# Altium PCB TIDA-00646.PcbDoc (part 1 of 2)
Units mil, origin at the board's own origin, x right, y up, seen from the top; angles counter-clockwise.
Board outline 1574.8 x 3450 mil, 2 copper layers (Top Layer, Bottom Layer), stack 38.583 mil thick; 90 components, 120 nets, 385 pads, 272 vias.
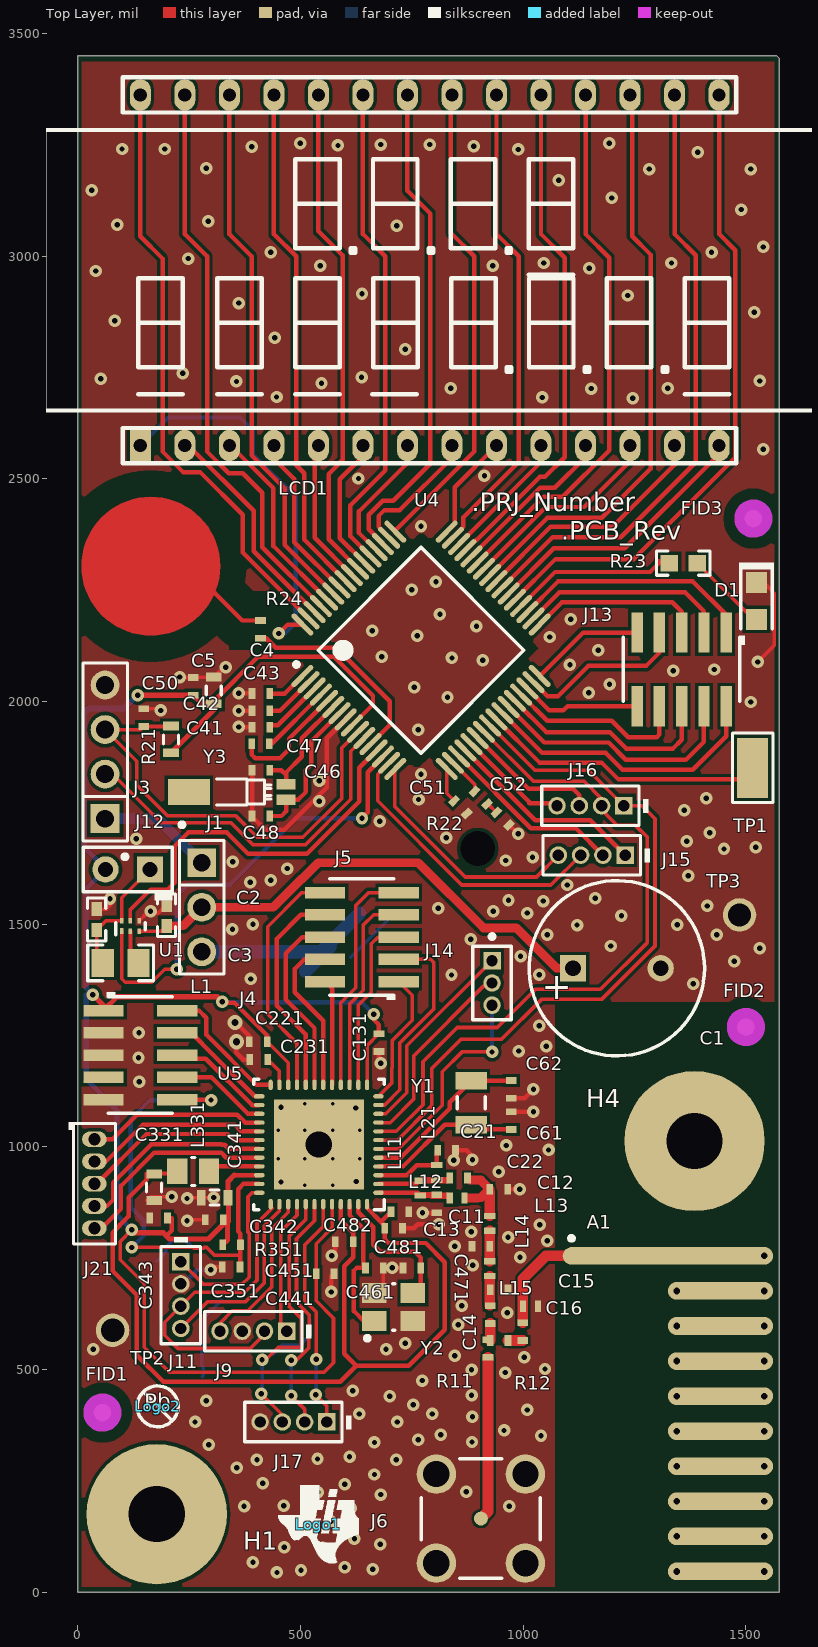
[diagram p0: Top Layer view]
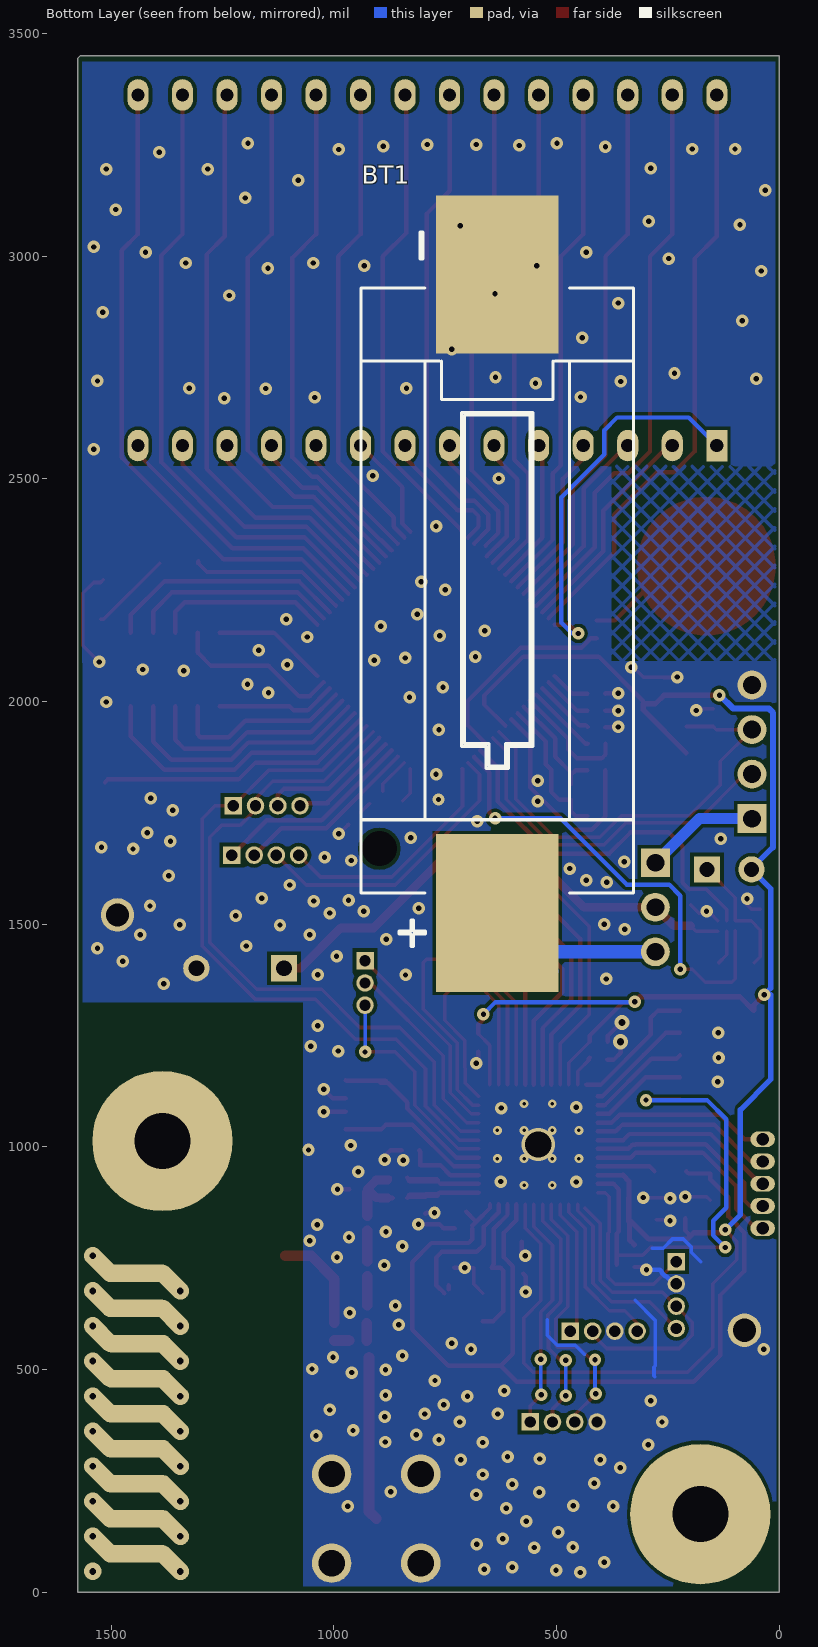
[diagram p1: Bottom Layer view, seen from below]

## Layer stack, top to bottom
Top Solder: solder mask 0.4, Solder Resist, Dk 3.5
Top Layer: signal copper 1.378
Dielectric1: core 35.8268, FR-4, Dk 4.6
Bottom Layer: signal copper 1.378
Bottom Solder: solder mask 0.4, Solder Resist, Dk 3.5

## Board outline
0,0 1574.8,0 1574.8,3445.2 1570,3450 0,3450

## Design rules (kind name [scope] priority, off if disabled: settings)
AssemblyTestPointUsage [All] p1: valid=2
Clearance Clearance_Keepouts [((IsTrack Or IsArc) And Not InPoly) And IsFree and IsKeepOut vs ((IsTrack Or IsArc) And Not InPoly) And IsFree and IsKeepOut] p1: gap=0
Clearance Clearance_BoardEdge_MountingHoles [OnCopper and InComponentClass('Mounting Holes') vs IsKeepOut] p2: gap=40
Clearance Clearance_BoardEdge_Poly [OnCopper and InPoly vs IsKeepOut] p3: gap=25
Clearance Clearance_BoardEdge [OnCopper and Not InComponentClass('Logo') and not InComponentClass('FiducialMark') and not InRegion(1000,500,4000,800) and Not IsKeepout vs IsKeepOut] p4: gap=75
Clearance Clearance_CAP [InNet('CAP_EL') vs InNet('GND')] p5: gap=59.06
Clearance Clearance_015 [InPolygon vs (InNet('NetC12_1') OR InNet('NetC13_1') OR InNet('NetC14_1') OR InNet('NetC15_2') OR InNet('NetC16_2') OR InNet('NetA1_1') OR InNet('NetJ6_1') )] p6: gap=5.91
Clearance Clearance_Poly [InPolygon] p7: gap=7.87
Clearance [All] p8: gap=7.87
ComponentClearance [All] p1: gap=10 collisioncheckmode=3 verticalgap=10 showdistances=TRUE
DiffPairsRouting [All] p1: maxlimit=100 minlimit=10 mostfreqgap=10 toplayer_minwidth=15 toplayer_maxwidth=15 toplayer_prefwidth=15 bottomlayer_minwidth=15 bottomlayer_maxwidth=15 bottomlayer_prefwidth=15 maxuncoupledlength=1000
FabricationTestPointUsage TestPointUsage [All] p1: valid=2 allowmultiple=FALSE
FabricationTestpoint Testpoint [All] p1: side=3 testpointundercomponent=TRUE minsize=40 maxsize=100 preferedsize=60 minholesize=0 maxholesize=40 preferedholesize=32 testpointgrid=1 allowsidetop=TRUE allowsidebottom=TRUE usegrid=TRUE gridtolerance=0.01
FanoutControl Fanout_LCC [IsLCC] p1: bgadir=Out bgaviamode=Centered fanoutstyle=Auto fanoutdirection=Alternating viagrid=1 // Fanout_LCC (Default Rule)
FanoutControl Fanout_BGA [IsBGA] p2: bgadir=Out bgaviamode=Centered fanoutstyle=Auto fanoutdirection=Alternating viagrid=1 // Fanout_BGA (Default Rule)
FanoutControl Fanout_Default [All] p4: bgadir=Out bgaviamode=Centered fanoutstyle=Auto fanoutdirection=Alternating viagrid=1 // Fanout_Default (Default Rule)
FanoutControl Fanout_Small [(CompPinCount < 5)] p5: bgadir=Out bgaviamode=Centered fanoutstyle=Auto fanoutdirection=OutThenIn viagrid=1 // Fanout_Small (Default Rule)
HoleSize [All] p1: absolutevalues=TRUE maxlimit=236.22 minlimit=7.87 maxpercent=80.000 minpercent=20.000
HoleSize FabricationTestpoint [All] p2 off: absolutevalues=TRUE maxlimit=100 minlimit=1 maxpercent=80.000 minpercent=20.000
HoleSize FabricationTestPointUsage [All] p3 off: absolutevalues=TRUE maxlimit=100 minlimit=1 maxpercent=80.000 minpercent=20.000
PlaneClearance [All] p1: clearance=7.87
PlaneConnect [All] p1: planeconnectstyle=Relief reliefexpansion=10 reliefentries=4 reliefconductorwidth=10 reliefairgap=10
PolygonConnect PolygonConnect_GND [HasPad('U5-49') OR HasPad('U4')] p1: connectstyle=NoConnect reliefconductorwidth=10 reliefentries=4 polygonreliefangle="90 Angle" airgapwidth=10
PolygonConnect [All] p2: connectstyle=Direct reliefconductorwidth=10 reliefentries=4 polygonreliefangle="90 Angle" airgapwidth=10
RoutingVias ThermalPadVias [IsVia and InAnyComponent] p1: holewidth=7.87 width=19.68 viastyle="Through Hole" minholewidth=7.87 minwidth=19.68 maxholewidth=15.35 maxwidth=23.62
RoutingVias [All] p2: holewidth=16 width=34 viastyle="Through Hole" minholewidth=11.81 minwidth=26 maxholewidth=40 maxwidth=65
SilkToSilkClearance [All] p1: silktosilkclearance=7.87
SilkToSolderMaskClearance [IsPad] p1: minsilkscreentomaskgap=7.87 clearancetoexposedcopper=TRUE
SolderMaskExpansion [All] p1: expansion=1.97
UnpouredPolygon [All] p1: allowunpoured=FALSE
Width [All] p1: maxlimit=100 minlimit=6 preferedwidth=10 checkconnectedcopper=TRUE
15 further rules are at their usual default settings.

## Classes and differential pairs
component class AssemblyNote: ZZ2 ZZ3 ZZ4
component class FiducialMark: FID1 FID2 FID3
component class TID_Hardware: FID1 FID2 FID3 H1 H4 Logo1 Logo2 ZZ2 ZZ3 ZZ4
component class Logo: Logo1
component class "Mounting Holes": H1 H4
component class TIDA-00646_MCU: BT1 C1 C2 C3 C4 C5 C41 C42 C43 C46 C47 C48 C50 C51 C52 D1 J1 J3 J12 J13 J14 J15 J16 L1 LCD1 R21 R22 R23 R24 TP1 TP2 TP3 U1 U4 Y3
component class TIDA-00646_RF: A1 C11 C12 C13 C14 C15 C16 C21 C22 C61 C62 C131 C221 C231 C331 C341 C342 C343 C351 C441 C451 C461 C471 C481 C482 J4 J5 J6 J9 J11 J17 J21 L11 L12 L13 L14 L15 L21 L331 R11 R12 R351 U5 Y1 Y2
component class Header: J1 J3 J4 J5 J9 J11 J12 J13 J14 J15 J16 J17 J21

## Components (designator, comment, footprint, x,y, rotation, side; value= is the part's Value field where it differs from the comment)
A1 "ANTENNA_HELICAL" ANTENNA_HELICAL 1108.46,755 r270 top locked net-tie
BT1 "1010" BAT_1010 633,2242 r90 bottom locked
C1 "EEUFM1A122" CAPPR5-10X20 1210.43,1401 r0 top locked
C2 "GRM155R60J225ME15D" 0402 199,1520 r90 top
C3 "GRM155R60J225ME15D" 0402 42,1510.38 r90 top
C4 "GRM188R61A106ME69" 0603S 305,2025 r90 top
C5 "GRM155R61E104KA87D" 0402S 259,2034 r90 top
C11 "Comment" 0402S 806,872 r90 top
C12 "GRM1555C1H2R7CA01D" 0402S 945,905 r0 top
C13 "GRM1555C1H6R2CA01D" 0402S 905,777 r180 top
C14 "GRM1555C1H3R3CA01D" 0402S 946,679 r0 top
C15 "GRM1555C1H101JA01D" 0402S 926,623 r270 top
C16 "GRM1555C1H1R0CA01D" 0402S 999,585 r270 top
C21 "GRM1555C1H101JA01D" 0402S 827.93,992.25 r180 top
C22 "GRM1555C1H3R6CA01D" 0402S 855,930 r0 top
C41 "GRM155R61E104KA87D" 0402S 411,1942 r0 top
C42 "GRM155R61E104KA87D" 0402S 411,1979 r0 top
C43 "GRM155R61E104KA87D" 0402S 411,2018 r0 top
C46 "GRM1555C1H120JA01D" 0402S 411,1846 r0 top
C47 "GRM155R61A105KE15D" 0402S 410,1905 r180 top
C48 "GRM1555C1H120JA01D" 0402S 411,1743 r0 top
C50 "GRM155R61H102KA01D" 0402S 148,1964 r90 top
C51 "GRM155R61H102KA01D" 0402S 859.14,1762.86 r135 top
C52 "GRM155R61H102KA01D" 0402S 954,1737 r135 top
C61 "Comment" 0402S 973,1059 r90 top
C62 "GRM1555C1H120JA01D" 0402S 973,1129 r270 top
C131 "GRM155R61E104KA87D" 0402S 676,1234 r270 top
C221 "GRM155R61E104KA87D" 0402S 405,1236 r180 top
C231 "Comment" 0402S 406,1196 r180 top
C331 "GRM188R60J226MEA0J" 0603S 171,909 r270 top
C341 "GRM188R60J226MEA0J" 0603S 307,886 r180 top
C342 "GRM155R61E104KA87D" 0402S 306,836 r180 top
C343 "GRM155R61E104KA87D" 0402S 181,840 r180 top
C351 "GRM155R61E104KA87D" 0402S 344,730 r180 top
C441 "GRM155R61E104KA87D" 0402S 555,715 r0 top
C451 "GRM155R61E104KA87D" 0402S 598,787 r180 top
C461 "DNM" 0402S 666,728 r0 top
C471 "DNM" 0402S 750,728 r180 top
C481 "GRM155R61E104KA87D" 0402S 709,817 r0 top
C482 "GRM155R61E104KA87D" 0402S 723,854 r0 top
D1 "LTST-C170KRKT" LED_LTST-C170 1524,2226 r90 top
FID1 "Fiducial" Fiducial10-20 55,403 r0 top
FID2 "Fiducial" Fiducial10-20 1500,1269 r0 top
FID3 "Fiducial" Fiducial10-20 1517,2411 r0 top
H1 "NY PMS 440 0025 PH" "NY PMS 440 0025 PH" 177,175 r0 top
H4 "NY PMS 440 0025 PH" "NY PMS 440 0025 PH" 1385,1013 r0 top
J1 "TSW-103-07-G-S" TSW-103-07-G-S 278,1538 r270 top
J3 "4x1 Header" TSW-104-07-G-S 61,1887 r90 top
J4 "BB02-BS101-KA8-025B00" Gradconn_BB02-BS101-xAx-025B00 140,1206 r0 top
J5 "DNP" Gradconn_BB02-BS101-xAx-025B00 637.68,1471 r180 top locked
J6 "SASF546-P26-X1" CONN_LTI_SASF546-P26-X1 905,165 r0 top locked
J9 "DNP" Preci-dip_850-xx-004-10-001101 394,586 r180 top
J11 "DNP" Preci-dip_850-xx-004-10-001101 231,667 r270 top
J12 "800-10-002-10-001000" Mill-Max_800-10-002-10-001000 112,1623 r180 top
J13 "DNP" Gradconn_BB02-BS101-xAx-025B00 1356,2072.32 r270 top
J14 "DNP" Mill-Max_850-10-003-10-001000 930,1368 r270 top
J15 "DNP" Preci-dip_850-xx-004-10-001101 1154,1655 r180 top
J16 "DNP" Preci-dip_850-xx-004-10-001101 1151,1766 r180 top
J17 "DNP" Preci-dip_850-xx-004-10-001101 484,382 r180 top
J21 "DNP" Sullins_GRPB051VWVN-RC 37,917 r270 top
L1 "LQM21PN2R2NGC" 0805_HV 96,1413 r180 top
L11 "LQW15AN18NJ00D" LQW15A_00_10 769,907 r270 top
L12 "LQW15AN7N5G00D" LQW15A_00_10 851.73,885 r0 top
L13 "LQW15AN6N8G00D" LQW15A_00_10 925,828.27 r270 top
L14 "LQW15AN6N8G00D" LQW15A_00_10 925,726.27 r270 top
L15 "LQW15AN12NJ00D" LQW15A_00_10 1016.27,642 r180 top
L21 "LQW15AN7N5G00D" LQW15A_00_10 806,942 r270 top
L331 "MLZ2012N6R8LT000" 0805_145 258.57,945 r180 top
LCD1 "DNP" LCD 140,2575 r0 top locked
Logo1 "Texas Instruments" TI_Symbol_Overlay_Small 540,152 r0 top
Logo2 "Pb-Free Symbol" Pb-Free_Overlay_Small 179,417 r0 top
R11 "CRCW04020000Z0ED" 0402S 921,547 r270 top
R12 "Comment" 0402S 946,565 r0 top
R21 "CRCW060347K0JNEA" 0603S 209,1915 r270 top
R22 "CRCW04020000Z0ED" 0402S 904.86,1784.14 r135 top
R23 "CRCW06031K20JNEA" 0603 1359.5,2311 r0 top
R24 "CRCW04020000Z0ED" 0402S 410,2162 r270 top
R351 "ERJ-2RKF1003X" 0402S 345,780 r180 top
TP1 "5015" Testpoint_Keystone_Miniature 1515,1851 r90 top
TP2 "1040" CONN_1040 78,588 r90 top
TP3 "1040" CONN_1040 1486,1521 r90 top
U1 "TPS62730DRYR" DRY0006A 118,1495.81 r90 top
U4 "DNP" PM0064A_M 770.48,2115.2 r45 top locked
U5 "CC1310F128RGZR" RGZ0048A 541.14,1005.16 r180 top locked
Y1 "FC-135 32.7680KA-A3" Epson_FC-135 883,1099 r90 top
Y2 "TSX-3225 24.0000MF20G-AC3" EPSON_TSX-3225 709,640 r90 top
Y3 "MS3V-T1R 32.768KHZ +/-20PPM 12.5PF" XTAL_MS3V-T1R 358.25,1797 r180 top
ZZ2 "These assemblies are ESD sensitive, ESD precautions shall be observed." AssemblyNote -3615,4399.11 r0 top
ZZ3 "These assemblies must be clean and free from flux and all contaminants. Use of no clean flux is not acceptable." AssemblyNote -3615,4310.56 r0 top
ZZ4 "These assemblies must comply with workmanship standards IPC-A-610 Class 2, unless otherwise specified." AssemblyNote -3615,4222 r0 top

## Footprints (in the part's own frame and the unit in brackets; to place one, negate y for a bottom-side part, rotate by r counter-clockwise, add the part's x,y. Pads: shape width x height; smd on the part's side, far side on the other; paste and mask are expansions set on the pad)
0402 [mm] "0402 from SM-752 data"
  rect 0.8x0.6 smd: 1(-0.6,0) 2(0.6,0)
  silkscreen extent -1.22,-0.52 1.22,0.52, body extent -0.55,-0.3 0.55,0.3, height 0.6
0402S [mil] "Based on C0402S footprint from PADS legacy"
  rect 15x24 smd: 1(-20,0) 2(20,0)
  body extent -22,-12 22,12, height 24
0603 [mm] "0603 from SM-752 data"
  rect 1x0.95 smd: 1(-0.8,0) 2(0.8,0)
  silkscreen extent -1.52,-0.69 1.52,0.69, body extent -0.87,-0.47 0.87,0.47, height 0.85
0603S [mil]
  rect 20x35 smd: 1(-30,0) 2(30,0)
  silkscreen extent -10,-17 10,17, body extent -34,-19 34,19, height 33
0805_145 [mm] "0805 / 1.45mm height"
  rect 1.15x1.45 smd: 1(-0.9,0) 2(0.9,0)
  silkscreen extent -0.1,-0.8 0.1,0.8, body extent -1.1,-0.72 1.1,0.72, height 1.45
0805_HV [mil] "0805 with 30mil clearance between pads"
  rect 50x63 smd: 1(-40,0) 2(40,0)
  silkscreen extent -74,-40 74,40, body extent -43,-29 43,29, height 57
ANTENNA_HELICAL [mm] "SMD, 1-Lead"
  round 1 smd paste-1 mask-1: 1(0,0)
  oval 1x12 smd paste-12 mask-12: ""(0,5.5)
  oval 1x2.414 smd far side rot 45 paste-1.5 mask-1.5: ""(0.5,10.5) ""(1.5,6.5) ""(2.5,10.5) ""(3.5,6.5) ""(4.5,10.5) ""(5.5,6.5) ""(6.5,10.5) ""(7.5,6.5) ""(8.5,10.5) ""(9.5,6.5) ""(10.5,10.5) ""(11.5,6.5) ""(12.5,10.5) ""(13.5,6.5) ""(14.5,10.5) ""(15.5,6.5) ""(16.5,10.5) ""(17.5,6.5)
  oval 1x4 smd far side paste-4 mask-4: ""(1,8.5) ""(3,8.5) ""(5,8.5) ""(7,8.5) ""(9,8.5) ""(11,8.5) ""(13,8.5) ""(15,8.5) ""(17,8.5)
  oval 1x6 smd paste-6 mask-6: ""(2,8.5) ""(4,8.5) ""(6,8.5) ""(8,8.5) ""(10,8.5) ""(12,8.5) ""(14,8.5) ""(16,8.5) ""(18,8.5)
  silkscreen extent -1.12,-0.12 -0.88,0.13
AssemblyNote [mil] "Assembly Note"
BAT_1010 [mm] "Keystone"
  round 0.94 hole 1.994 unplated: 0(-14.54,6.73)
  rect 9x7 smd: 1(-18.21,0) 2(18.21,0)
  silkscreen extent -20.12,-7.77 20.64,7.77, body extent -21.7,-7.77 22.07,7.77, height 15.06
CAPPR5-10X20 [mm] "Capacitor, Electrolytic, Radial; Body 10 x 20 mm (Dia.xH typ); Pin Spacing 5 mm (typ)"
  rect 1.5x1.5 hole 0.9: 1(-2.5,0)
  round 1.5 hole 0.9: 2(2.5,0)
  silkscreen extent -5,-5 5,5, body extent -5.01,-5.01 5.01,5.01, height 22
CONN_1040 [mil] "Test Point, PC  test point Terminal"
  round 75 hole 52: 1(0,0)
  body extent -55,-12 55,13, height 276
CONN_LTI_SASF546-P26-X1 [mm]
  round 0.8 smd: 1(0,0)
  round 2.25 hole 1.5 mask+0.051: 2(-2.54,2.54) 3(-2.54,-2.54) 4(2.54,-2.54) 5(2.54,2.54)
  silkscreen extent -3.4,-3.4 3.4,3.4, body extent -3.17,-3.17 3.17,3.17, height 12.53
DRY0006A [mm] "PSON, 6-Leads, Body 1x1.45mm, Pitch 0.5mm, TI Recommended"
  rect 0.35x0.2 smd: 1(-0.275,0.5)
  rect 0.3x0.2 smd: 2(-0.3,0) 3(-0.3,-0.5) 4(0.3,-0.5) 5(0.3,0) 6(0.3,0.5)
  silkscreen extent -0.5,-0.85 0.2,0.85, body extent -0.53,-0.75 0.53,0.75, height 0.61
Epson_FC-135 [mm] "SMD, 2-Leads, Body 3.2x1.5mm"
  rect 1x1.8 smd: 1(-1.25,0) 2(1.25,0)
  silkscreen extent -0.35,-0.8 0.35,0.8, body extent -1.65,-0.8 1.65,0.8, height 0.9
EPSON_TSX-3225 [mm] "SMD, 4-Leads, Body 2.65x3.35mm, Height 0.6mm"
  rect 1.15x1.4 smd: 1(-0.8,1.1) 2(-0.8,-1.1) 3(0.8,-1.1) 4(0.8,1.1)
  silkscreen extent -1.9,-0.05 1.33,1.62, body extent -1.33,-1.68 1.33,1.68, height 0.61
Fiducial10-20 [mm]
  round 1 smd mask+0.5: 1(0,0)
  Top Layer keep-out circle w1.178: c0,0 r0.5
Gradconn_BB02-BS101-xAx-025B00 [mm] "Header, 1.27mm, 5x2, SMT"
  rect 2.3x0.65 smd: 1(-2.1,2.54) 2(2.1,2.54) 3(-2.1,1.27) 4(2.1,1.27) 5(-2.1,0) 6(2.1,0) 7(-2.1,-1.27) 8(2.1,-1.27) 9(-2.1,-2.54) 10(2.1,-2.54)
  silkscreen extent -1.92,-3.32 1.83,3.6, body extent -2.75,-3.32 2.75,3.32, height 4.25
LCD [mm]
  rect 1.2x1.8 hole 0.75: 1(0,0)
  oval 1.2x1.8 hole 0.75: 2(2.54,0) 3(5.08,0) 4(7.62,0) 5(10.16,0) 6(12.7,0) 7(15.24,0) 8(17.78,0) 9(20.32,0) 10(22.86,0) 11(25.4,0) 12(27.94,0) 13(30.48,0) 14(33.02,0) 15(33.02,20) 16(30.48,20) 17(27.94,20) 18(25.4,20) 19(22.86,20) 20(20.32,20) 21(17.78,20) 22(15.24,20) 23(12.7,20) 24(10.16,20) 25(7.62,20) 26(5.08,20) 27(2.54,20) 28(0,20)
  silkscreen extent -5.5,-1 38.5,21
LED_LTST-C170 [mm] "LITE-ON"
  rect 1.2x1.2 smd: 1(-1.05,0) 2(1.05,0)
  silkscreen extent -1.6,-1 2.2,1, body extent -1.05,-0.67 1.05,0.67, height 1.1
LQW15A_00_10 [mm] "Murata"
  rect 0.35x0.65 smd: 1(-0.425,0) 2(0.425,0)
  body extent -0.55,-0.35 0.55,0.35, height 0.6
Mill-Max_800-10-002-10-001000 [mm] "Mill-Max"
  rect 1.5x1.5 hole 0.85: 1(-1.27,0)
  round 1.5 hole 0.85: 2(1.27,0)
  silkscreen extent -2.54,-1.27 2.54,1.78, body extent -2.54,-1.27 2.54,1.27, height 8.13
Mill-Max_850-10-003-10-001000 [mm] "Header, 1.27 mm, 3x1, Gold, Straight, TH"
  rect 1x1 hole 0.65: 1(-1.27,0)
  round 1 hole 0.65: 2(0,0) 3(1.27,0)
  silkscreen extent -2.77,-1.1 2.09,1.1, body extent -2.1,-1.1 2.1,1.1, height 5.21
"NY PMS 440 0025 PH" [mm] "4-40 nylon screw and mounting hole"
  round 8 hole 3.2: 1(0,0)
  body extent -3.3,-3.3 3.3,3.3, height 2.69
Pb-Free_Overlay_Small [mil]
  silkscreen extent -46,-46 46,46
PM0064A_M [mm] "Thin QFP, 64-Leads, Body 10x10mm, Pitch 0.5mm, IPC Low Density"
  oval 1.65x0.3 smd: 1(-5.825,3.75) 2(-5.825,3.25) 3(-5.825,2.75) 4(-5.825,2.25) 5(-5.825,1.75) 6(-5.825,1.25) 7(-5.825,0.75) 8(-5.825,0.25) 9(-5.825,-0.25) 10(-5.825,-0.75) 11(-5.825,-1.25) 12(-5.825,-1.75) 13(-5.825,-2.25) 14(-5.825,-2.75) 15(-5.825,-3.25) 16(-5.825,-3.75) 33(5.825,-3.75) 34(5.825,-3.25) 35(5.825,-2.75) 36(5.825,-2.25) 37(5.825,-1.75) 38(5.825,-1.25) 39(5.825,-0.75) 40(5.825,-0.25) 41(5.825,0.25) 42(5.825,0.75) 43(5.825,1.25) 44(5.825,1.75) 45(5.825,2.25) 46(5.825,2.75) 47(5.825,3.25) 48(5.825,3.75)
  oval 0.3x1.65 smd: 17(-3.75,-5.825) 18(-3.25,-5.825) 19(-2.75,-5.825) 20(-2.25,-5.825) 21(-1.75,-5.825) 22(-1.25,-5.825) 23(-0.75,-5.825) 24(-0.25,-5.825) 25(0.25,-5.825) 26(0.75,-5.825) 27(1.25,-5.825) 28(1.75,-5.825) 29(2.25,-5.825) 30(2.75,-5.825) 31(3.25,-5.825) 32(3.75,-5.825) 49(3.75,5.825) 50(3.25,5.825) 51(2.75,5.825) 52(2.25,5.825) 53(1.75,5.825) 54(1.25,5.825) 55(0.75,5.825) 56(0.25,5.825) 57(-0.25,5.825) 58(-0.75,5.825) 59(-1.25,5.825) 60(-1.75,5.825) 61(-2.25,5.825) 62(-2.75,5.825) 63(-3.25,5.825) 64(-3.75,5.825)
  silkscreen extent -5.72,-4.15 4.15,4.57, body extent -6,-6 6,6, height 1.49
Preci-dip_850-xx-004-10-001101 [mm] "Preci-dip"
  rect 1x1 hole 0.65: 1(-1.905,0)
  round 1 hole 0.65: 2(-0.635,0) 3(0.635,0) 4(1.905,0)
  silkscreen extent -3.33,-1.12 2.78,1.12, body extent -2.74,-1.1 2.74,1.1, height 5.2
RGZ0048A [mm] "QFN, 48-Leads, Body 7x7mm, Pitch 0.5mm, Thermal Pad 5.15X5.15mm, TI recommended"
  oval 0.6x0.24 smd: 1(-3.4,2.75) 2(-3.4,2.25) 3(-3.4,1.75) 4(-3.4,1.25) 5(-3.4,0.75) 6(-3.4,0.25) 7(-3.4,-0.25) 8(-3.4,-0.75) 9(-3.4,-1.25) 10(-3.4,-1.75) 11(-3.4,-2.25) 12(-3.4,-2.75) 25(3.4,-2.75) 26(3.4,-2.25) 27(3.4,-1.75) 28(3.4,-1.25) 29(3.4,-0.75) 30(3.4,-0.25) 31(3.4,0.25) 32(3.4,0.75) 33(3.4,1.25) 34(3.4,1.75) 35(3.4,2.25) 36(3.4,2.75)
  oval 0.24x0.6 smd: 13(-2.75,-3.4) 14(-2.25,-3.4) 15(-1.75,-3.4) 16(-1.25,-3.4) 17(-0.75,-3.4) 18(-0.25,-3.4) 19(0.25,-3.4) 20(0.75,-3.4) 21(1.25,-3.4) 22(1.75,-3.4) 23(2.25,-3.4) 24(2.75,-3.4) 37(2.75,3.4) 38(2.25,3.4) 39(1.75,3.4) 40(1.25,3.4) 41(0.75,3.4) 42(0.25,3.4) 43(-0.25,3.4) 44(-0.75,3.4) 45(-1.25,3.4) 46(-1.75,3.4) 47(-2.25,3.4) 48(-2.75,3.4)
  rect 5.15x5.15 smd paste-2.6: 49(0,0)
  silkscreen extent -3.73,-3.72 3.73,3.72, body extent -3.58,-3.57 3.57,3.58, height 1.01
Sullins_GRPB051VWVN-RC [mm] "SULLINS"
  oval 0.9x1.4 hole 0.7: 1(-2.54,0) 2(-1.27,0) 3(0,0) 4(1.27,0) 5(2.54,0)
  silkscreen extent -3.53,-1.48 3.45,1.2, body extent -3.42,-1.17 3.42,1.17, height 4.2
Testpoint_Keystone_Miniature [mil] "Miniature SMT test point"
  rect 135x70 smd: 1(0,0)
  silkscreen extent -78,-46 78,45, body extent -52,-20 52,20, height 61
TI_Symbol_Overlay_Small [mil]
  silkscreen extent -90,-88 91,88
TSW-103-07-G-S [mm]
  rect 1.65x1.65 hole 1.016 mask+0: 1(-2.54,0)
  round 1.65 hole 1.016 mask+0: 2(0,0) 3(2.54,0)
  silkscreen extent -4.83,-1.27 3.81,1.27, body extent -3.81,-1.27 3.81,1.27, height 8.38
TSW-104-07-G-S [mm]
  rect 1.65x1.65 hole 1.016 mask+0: 1(-3.81,0)
  round 1.65 hole 1.016 mask+0: 2(-1.27,0) 3(1.27,0) 4(3.81,0)
  silkscreen extent -6.1,-1.27 5.08,1.27, body extent -5.08,-1.27 5.08,1.27, height 8.38
XTAL_MS3V-T1R [mm] "Micro Crystal Switzerland recommended land pattern"
  rect 1.1x0.6 smd: 1(-2.775,0.45) 2(-2.775,-0.45)
  rect 2.4x1.5 smd: 3(2.775,0)
  silkscreen extent -1.9,-0.74 1.2,0.74, body extent -3.05,-0.74 3.65,0.74, height 1.42

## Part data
A1: "PCB Antenna. There is nothing to buy or mount."
BT1: "Battery Holder, Nylon, CR2, SMT"
C1: "CAP, AL, 1200 µF, 10 V, +/- 20%, TH"
C2 C3: "CAP, CERM, 2.2 µF, 6.3 V, +/- 20%, X5R, 0402"
C4: "CAP, CERM, 10 µF, 10 V, +/- 20%, X5R, 0603"
C5 C41 C42 C43 C131 C221 C342 C343 C351 C441 C451 C481 C482: "CAP, CERM, 0.1 µF, 25 V, +/- 10%, X5R, 0402"
C11: library part GRM1555C1H3R6CA01D, "CAP, CERM, 3.6 pF, 50 V, +/- 5%, C0G/NP0, 0402"
C12: "CAP, CERM, 2.7 pF, 50 V, +/- 5%, C0G/NP0, 0402"
C13: "CAP, CERM, 6.2 pF, 50 V, +/- 5%, C0G/NP0, 0402"
C14: "CAP, CERM, 3.3 pF, 50 V, +/- 5%, C0G/NP0, 0402"
C15 C21: "CAP, CERM, 100 pF, 50 V, +/- 5%, C0G/NP0, 0402"
C16: "CAP, CERM, 1 pF, 50 V, +/- 5%, C0G/NP0, 0402"
C22: "CAP, CERM, 3.6 pF, 50 V, +/- 5%, C0G/NP0, 0402"
C46 C48 C62: "CAP, CERM, 12 pF, 50 V, +/- 5%, C0G/NP0, 0402"
C47: "CAP, CERM, 1 µF, 10 V, +/- 10%, X5R, 0402"
C50 C51 C52: "CAP, CERM, 1000 pF, 50 V, +/- 10%, X5R, 0402"
C61 C461 C471: library part GRM1555C1H120JA01D, "CAP, CERM, 12 pF, 50 V, +/- 5%, C0G/NP0, 0402"
C231: library part GRM155R61A105KE15D, "CAP, CERM, 1 µF, 10 V, +/- 10%, X5R, 0402"
C331 C341: "CAP, CERM, 22 µF, 6.3 V, +/- 20%, X5R, 0603"
D1: "LED, Green, SMD"
FID1 FID2 FID3: "Fiducial mark.  There is nothing to buy or mount."
H1 H4: "Machine Screw, Round, #4-40 x 1/4, Nylon, Philips panhead"
J1: "Header, TH, 100mil, 3x1, Gold plated, 230 mil above insulator"
J3: library part TSW-104-07-G-S, "Header, TH, 100mil, 4x1, Gold plated, 230 mil above insulator"
J4: "Header, 1.27mm, 5x2, SMT"
J5 J13: library part BB02-BS101-KA8-025B00, "Header, 1.27mm, 5x2, SMT"
J6: "Connector, SMA,Vertical, Thru hole w/SMT center pin"
J9 J11 J15 J16 J17: library part 850-10-004-10-001101, "Header, 50mil, 4x1, Gold, TH"
J12: "Header, 100mil, 2x1, TH"
J14: library part 850-10-003-10-001000, "Header, 50mil, 3x1, Gold, TH"
J21: library part GRPB051VWVN-RC, "Header, 50mil, 5x1, Gold, TH"
L1: "Inductor, Shielded, Ferrite, 2.2 µH, 0.8 A, 0.23 ohm, SMD"
L11: "Inductor, Wirewound, 18 nH, 0.37 A, 0.27 ohm, SMD"
L12 L21: "Inductor, Wirewound, 7.5 nH, 0.57 A, 0.13 ohm, SMD"
L13 L14: "Inductor, Wirewound, 6.8 nH, 0.7 A, 0.09 ohm, SMD"
L15: "Inductor, Wirewound, 12 nH, 0.5 A, 0.14 ohm, SMD"
L331: "Inductor, Multilayer, Ferrite, 6.8 µH, 0.11 A, 0.25 ohm, SMD"
LCD1: library part LCD_4MUX, "BTL002 4COM LCD"
Logo1: library part TI_Logo, "Texas Instrument Corporate Signature"
Logo2: library part Pb-Free
R11 R22 R24: "RES, 0, 5%, 0.063 W, 0402"
R12: library part CRCW04020000Z0ED, "RES, 0, 5%, 0.063 W, 0402"
R21: "RES, 47 k, 5%, 0.1 W, 0603"
R23: "RES, 1.2 k, 5%, 0.1 W, 0603"
R351: "RES, 100 k, 1%, 0.1 W, 0402"
TP1: "Test Point, Miniature, SMT"
TP2 TP3: "TEST POINT SLOTTED .118\", TH"
U1: "Buck Step Down Regulator with 1.9 to 3.9 V Input and 2.1 V Output, -40 to 85 degC, 6-Pin SON (DRY), Green (RoHS & no Sb/Br)"
U4: library part MSP430G60x1, "16-bit Ultra-Low-Power MCU"
U5: "Sub-1 GHz and 2.4 GHz Multi-standard RF IC Family, RGZ0048A"
Y1: "Crystal, 32.768 KHz, 12.5 pF, SMD"
Y2: "Crystal, 24 MHz, 9 pF, SMD"
Y3: "Crystal, 32.768kHz, 12.5pF, SMD"
ZZ2 ZZ3 ZZ4: library part AssemblyNote

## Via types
v1: diameter 28, hole 12, Top Layer to Bottom Layer, 238 vias
v2: diameter 39.37, hole 14.96, Top Layer to Bottom Layer, 19 vias
v3: diameter 19.68, hole 7.87, Top Layer to Bottom Layer, 12 vias
v4: diameter 34, hole 16, Top Layer to Bottom Layer, 2 vias
v5: diameter 74.8, hole 59.06, Top Layer to Bottom Layer, 1 vias

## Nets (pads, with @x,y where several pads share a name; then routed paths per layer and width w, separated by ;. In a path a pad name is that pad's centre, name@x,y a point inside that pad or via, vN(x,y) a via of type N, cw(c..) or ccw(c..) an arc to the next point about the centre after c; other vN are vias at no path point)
ACLK: J15.3 U4.15 | length 658.3
  Top Layer w8: U4.15@698.79,1862.56 673,1836.77 673,1777 862,1588 1062,1588 J15.3@1129,1655
BAT_IN: BT1.1 J1.3 | length 609.6
  Bottom Layer w8: BT1.1@613,1426 BT1.1@713,1526
  Bottom Layer w30: J1.3@278,1438 545.93,1438 BT1.1@633,1525.07 ; BT1.1@511,1394 BT1.1@565.5,1448.5
BYP_TPS: U1.5 U4.13 | length 858.6
  Top Layer w7.87: U1.5@118,1507.62 118,1533 163,1578 202,1578
  Top Layer w10: 202,1578 217,1593 217,1675 248,1706 334,1706 382,1658 514.31,1658 632,1775.69 632,1851.45 U4.13@670.95,1890.4
CAP_EL: R24.1 | length 127.3
  Top Layer w10: 308,2243 369,2182 R24.1@410,2182
CAPT: R24.2 U4.12 | length 462.9
  Top Layer w10: R24.2@410,2142 423,2142 444,2121 580,2121 700,2001 700,1947.29 U4.12@657.03,1904.32
CAPT1: R22.2 U4.18 | length 84.4
  Top Layer w8: U4.18@842.16,1862.56 890.72,1814.01 R22.2@890.72,1798.28
CAPT2: C51.2 U4.17 | length 78.6
  Top Layer w8: U4.17@828.24,1848.64 828.24,1793.76 C51.2@845,1777
DCDC_SW: L331.1 U5.33 | length 132
  Top Layer w10: L331.1@279.87,945 290.81,955.94 U5.33@407.28,955.94
"DIO16 / JTAG TDO": J4.6 U5.26 | length 231.1
  Top Layer w10: J4.6@222.68,1206 230.68,1198 287,1198 391.26,1093.74 U5.26@407.28,1093.74
"DIO17 / JTAG TDI": J4.8 U5.27 | length 218.5
  Top Layer w10: J4.8@222.68,1156 299.83,1156 381.78,1074.05 U5.27@407.28,1074.05
DIO_1: J14.3 U5.6 | length 494.5
  Top Layer w8: U5.6@675,995.31 720.45,995.31 818.13,1092.99 818.13,1168.68 862.44,1213 v1(930,1213)
  Bottom Layer w8: v1(930,1213) J14.3@930,1318
DIO_4: J14.2 U5.9 | length 441.7
  Top Layer w8: U5.9@675,1054.37 701.37,1054.37 754.62,1107.62 754.62,1204.62 911,1361 923,1361 J14.2@930,1368
DIO_5: J14.1 U5.10 | length 459.3
  Top Layer w8: U5.10@675,1074.05 691.6,1074.05 738.75,1121.2 738.75,1226.75 J14.1@930,1418
DIO_6: J5.3 U5.11 | length 461.3
  Top Layer w8: U5.11@675,1093.74 688.85,1093.74 722.88,1127.77 722.88,1233.32 799,1309.44 799,1414 792,1421 J5.3@720.35,1421
DIO_7: J5.1 U5.12 | length 301.8
  Top Layer w8: U5.12@675,1113.42 675.07,1113.42 705,1143.36 705,1176.41 705.87,1177.28 705.87,1238.76 751,1283.89 751,1340.35 J5.1@720.35,1371
DIO_8: J5.5 U5.14 | length 396.7
  Top Layer w8: U5.14@629.72,1139.01 629.72,1317.72 659,1347 659,1456 674,1471 J5.5@720.35,1471
DIO_9: J5.7 U5.15 | length 460.7
  Top Layer w8: U5.15@610.04,1139.01 610.04,1320.48 641.13,1351.57 641.13,1498.13 664,1521 J5.7@720.35,1521
DIO_10: J5.9 U5.16 | length 525.3
  Top Layer w8: U5.16@590.35,1139.01 590.35,1323.24 624.03,1356.92 624.03,1542.03 653,1571 J5.9@720.35,1571
DIO_11: J5.2 U5.17 | length 238.5
  Top Layer w10: J5.2@555,1371 570.67,1355.33 U5.17@570.67,1139.01
DIO_12: J5.4 U5.18 | length 363.6
  Top Layer w10: U5.18@550.98,1139.01 550.98,1283.02 487.2,1346.8 487.2,1399.54 508.66,1421 J5.4@555,1421
DIO_13: J5.6 U5.19 | length 424.9
  Top Layer w10: U5.19@531.3,1139.01 531.3,1266.7 467,1331 467,1434 504,1471 J5.6@555,1471
DIO_14: J5.8 U5.20 | length 485.4
  Top Layer w10: U5.20@511.61,1139.01 511.61,1252.39 447,1317 447,1467.44 500.56,1521 J5.8@555,1521
DIO_15: J5.10 U5.21 | length 543.2
  Top Layer w8: U5.21@491.93,1139.01 491.93,1232.07 426,1298 426,1494 503,1571 J5.10@555,1571
DIO_18: J21.1 U5.28 | length 400.4
  Top Layer w10: J21.1@37,1017 77.68,1017 132.68,1072 358,1072 375.63,1054.37 U5.28@407.28,1054.37
DIO_19: J21.2 U5.29 | length 411
  Top Layer w10: J21.2@37,967 63,967 146,1050 351.68,1050 367,1034.68 U5.29@407.28,1034.68
DIO_20: J21.3 U5.30 | length 422.3
  Top Layer w10: J21.3@37,917 42.22,917 154,1028.78 336.76,1028.78 350.54,1015 U5.30@407.28,1015
DIO_21: J21.4 U5.31 | length 455.2
  Top Layer w10: J21.4@37,867 65.18,867 78.76,880.57 78.76,919.45 165,1005.7 165,1006 322,1006 323.13,1004.87 329.4,1004.87 338.96,995.31 U5.31@407.28,995.31
DIO_22: J21.5 U5.32 | length 475.5
  Top Layer w10: J21.5@37,817 53,817 96.63,860.63 96.63,912.05 171.58,987 322,987 333.37,975.63 U5.32@407.28,975.63
DIO_28: J17.3 U5.41 | length 605.4
  Top Layer w8: v1(412,445) 459,398 J17.3@459,382 ; v1(413.54,521.87) 421.87,521.87 449.87,549.87 497.87,549.87 502.04,554.04 502.04,613.96 475,641 475,800.13 511.61,836.74 U5.41@511.61,871.3
  Bottom Layer w8: v1(412,445) 412,454 413.54,455.54 v1(413.54,521.87)
DIO_29: J17.2 U5.42 | length 554.2
  Top Layer w8: v1(479,441) 509,411 J17.2@509,382 ; v1(479,521) 491.44,521 517.91,547.46 517.91,585.35 519.28,586.72 519.28,622.28 493.13,648.43 493.13,649.87 490.87,652.13 490.87,793.55 531.3,833.98 U5.42@531.3,871.3
  Bottom Layer w8: v1(479,441) v1(479,521)
DIO_30: J17.1 U5.43 | length 530.4
  Top Layer w8: v1(534,443) 559,418 J17.1@559,382 ; v1(535,523) 535.15,523.15 535.15,628.85 509,655 509,779 550.98,820.98 U5.43@550.98,871.3
  Bottom Layer w8: v1(534,443) 535,442 v1(535,523)
GND: BT1.2 C1.2 C2.2 C3.2 C4.2 C5.2 C11.1 C12.2 C13.2 C14.2 C21.1 C41.1 C42.1 C43.1 C46.1 C48.1 C50.2 C51.1 C52.1 C61.2 C62.2 C131.2 C221.2 C231.2 C331.2 C341.2 C342.2 C343.2 C351.2 C441.2 C451.2 C461.2 C471.2 C481.2 C482.2 D1.2 J3.4 J4.3 J4.5 J4.9 J6.2 J6.3 J6.4 J6.5 J9.3 J11.2 J17.4 L15.1 TP2.1 TP3.1 U1.4 U4.8 U5.49 Y2.2 Y2.4 | length 2477.5
  Top Layer w7.87: C3.2@42,1534 63,1534 v1@73,1544 ; U1.4@137.69,1507.62 155.06,1525 180.38,1525 C2.2@199,1543.62 ; Y2.4@665.69,671.5 686,691.8 C461.2@686,728 v1(706,728)
  Top Layer w8: C50.2@148,1984 182,1984 v1(186,1980) ; C331.2@155,880 163,888 v1(211,888) ; v1(229,2055) 230,2054 C5.2@259,2054 260,2055 C4.2@305,2055 327,2077 v1(332,2077) ; v1(245,834) 247,836 276,836 ; v1(245,884) 247,886 C341.2@277,886 v1(305,886) v1@307,886 ; D1.2@1518,2273.34 D1.2@1524,2267.34 1539.66,2267.34 1564,2243 1564,2126 v1(1527,2089)
  Top Layer w10: v1@296,722 v1(298,724) 304,730 C351.2@324,730 ; v4(353,1279) 354,1280 385,1249 C221.2@385,1236 ; v4(356,1236) 356,1211 371,1196 C231.2@386,1196 ; v1@360,1979 v1(361.13,1979) C42.1@391,1979 ; v1(361,1943) 362,1942 C41.1@391,1942 ; v1(361.13,2019) 390,2019 C43.1@391,2018 ; C46.1@391,1846 C48.1@391,1743 391,1741.86 420.99,1711.87 463.87,1711.87 559,1807 559,1917.64 U4.8@601.36,1960 ; v1(569,674) 569,709 C441.2@575,715 ; v1(570,755) 578,763 C451.2@578,787 ; C131.2@676,1214 676,1193 681,1188 v1(680,1188) ; v1(706,728) C471.2@730,728 ; C481.2@729,817 754,817 763,826 v1(810,826) ; v1(774,852) 793,852 C11.1@795,850 ; C21.1@847.93,992.25 872.75,992.25 886,979 v1(886,971) ; C12.2@965,905 v1(992,905) ; C52.1@968.14,1722.86 988,1703 v1(989,1703) ; C61.2@973,1079 v1(1023,1079) ; C62.2@973,1109 1003,1109 v1(1023,1129)
  Bottom Layer w8: 176,742 197,763 197,775 215,793 239.41,793 260.28,772.13 284.87,772.13 ; 279,484 281,486 281,505 278,508 278,610 323,655 ; 438,534 458,554 498.11,554 521,576.89 521,611
  Bottom Layer w10: J11.2@231,692 236,692 253.44,709.44 256.02,709.44 263.56,716.98 263.56,719.56 268,724 v1(298,724) v1@297,723
  other v1: 447,44 501,49 662,51 599,56 393,67 550,100 463,101 679,107 621,120 496,134 568,159 613,188 373,193 969,193 462,194 680,219 539,224 872,225 599,242 415,244 666,264 357,279 402,297 715,297 538,299 610,304 294,331 666,336 885,337 764,342 1040,351 815,353 957,363 263,382 717,382 886,394 632,400 796,400 1009,409 753,421 288,430 700,440 884,442 617,452 773,475 960,493 884,499 1049,501 1002,527 846,531 34.5,545 692,545 735,559 854,600 964,627 861.76,643.23 887,734 993,752 846,777 1054,789 966,797 883,809 1037,825 456,921 625,922 945,944 844,970 1057,993 962,1003 624,1087 456,1089 138,1146 136,1200 990,1215 1052,1226 137,1256 1036,1272 1382,1366 388,1377 839,1386 1036.09,1386.1 1474,1417 994,1428 1531,1446 1197,1451 882,1466 1054,1476 1435,1476 347,1489 1121,1498 1346,1499 393,1500 1220.69,1518.77 1009,1525 163,1529 933,1529 809,1536 1413,1541 1045,1552 967,1554 72,1557 1162,1558 1099,1588 387,1594 433,1599 1371,1609 470,1625 348,1640 961,1643 1021,1650 1451,1669 1522,1673 1367,1686 131,1692 827,1694 1419,1705 678,1731 1362,1756 542,1776 765,1780 1411,1783 542,1822 770.48,1836.81 764,1937 1511,1999 830,2010 1147,2020 755,2032 1194,2039 1337,2069 1429,2072 1105,2083 909,2093 840,2098 682,2101 1168.57,2115.2 1060,2145 762,2148 661,2159 895,2169 1107,2185 813,2196 750,2251 804,2269 770.48,2393.59 630,2501 913,2507 1539,2567 1246,2681 1043,2683 446,2684 1153,2703 837,2704 1325,2704 547,2715 356,2719 1531,2720 51,2725 637,2728 235,2737 735,2791 442,2817 83,2855 1519,2874 361,2895 1235,2912 638,2916 40,2967 1148,2973 544,2979 932,2979 1046,2985 1333,2985 248,2995 433,3009 1423,3009 1539,3021 716,3069 88,3071 293,3079 1490,3105 1199,3131 31,3148 1080,3171 1283,3196 1511,3196 288,3198 1392,3234 989,3240 99,3241 195,3241 390,3246 889,3247 584,3249 680,3251 790,3251 499,3254 1193,3254
  other v3: 509.51,913.62 572.78,913.62 449.61,973.52 509.51,973.52 572.78,973.52 632.68,973.52 449.61,1036.79 509.51,1036.79 572.78,1036.79 632.68,1036.79 509.51,1096.69 572.78,1096.69
  other v5: 541.14,1005.16
JTAG_TCK: J4.4 U5.25 | length 243.7
  Top Layer w10: J4.4@222.68,1256 254.27,1256 304,1206.28 396.85,1113.42 U5.25@407.28,1113.42
JTAG_TMS: J4.2 U5.24 | length 301.6
  Top Layer w10: J4.2@222.68,1306 272,1306 288,1290 288,1252 400.99,1139.01 U5.24@432.87,1139.01
LCDCAP0: C47.2 U4.5 | length 263.8
  Top Layer w10: C47.2@390,1905 390,1881 398,1873 454,1873 474,1893 474,1916.16 U4.5@559.6,2001.76
LCDCAP1: C47.1 U4.4 | length 161.5
  Top Layer w10: C47.1@430,1905 435,1905 U4.4@545.68,2015.68
LED: R23.1 U4.36 | length 353.6
  Top Layer w10: U4.36@995.27,2214.73 1071.55,2291 1285,2291 1305,2311 1305,2315
LMT1_AIN: J11.1 U5.36 | length 392
  Top Layer w8: J11.1@231,742 282,691 368,691 384.37,707.37 384.37,805.5 381.87,808 381.87,887.87 390.89,896.89 U5.36@407.28,896.89
LMT1_ON: J11.4 U5.38 | length 421.1
  Top Layer w8: J11.4@231,592 291,652 376.45,652 418,693.55 418,821.45 452.56,856.01 U5.38@452.56,871.3
LMT2_AIN: J9.4 U5.39 | length 383.1
  Top Layer w8: J9.4@319,586 319,604 346.5,631.5 381.5,631.5 435,685 435,816 472.24,853.24 U5.39@472.24,871.3 ; J9.4@322,586 322,575 J9.4@324,573
LMT2_ON: J9.1 U5.40 | length 306.4
  Top Layer w8: J9.1@469,586 455,600 455,809 491.93,845.93 U5.40@491.93,871.3
LMT_ENB: J9.2 J11.3 U5.37 | length 707.6
  Top Layer w8: J9.2@419,586 419,579 387,547 224.86,547 195,576.86 195,606 J11.3@231,642 262,673 375,673 402.13,700.13 402.13,828.02 U5.37@435.96,861.86
NetA1_1: A1.1 C16.1 L15.2 | length 229
  Top Layer w24: C16.1@999,605 999,702.93 1051.07,755 A1.1@1108.46,755
NetC11_2: C11.2 L11.2 L12.1 U5.1 | length 164.9
  Top Layer w10: U5.1@675,896.89 763.65,896.89 L11.2@769,891.54 ; 793.46,891.54 C11.2@795,890 ; L12.1@830,890 L12.1@835,885
  Top Layer w14: L11.2@769,891.54 793.46,891.54 ; C11.2@795,890 L12.1@830,890
NetC12_1: C12.1 C22.2 L12.2 L13.1 | length 183
  Top Layer w10: C22.2@875,930 C22.2@880,925 ; C12.1@921.22,901.22 C12.1@925,897.44
  Top Layer w11.81: L12.2@868.46,885 887,885
  Top Layer w20: 879,885 897,885 ; C22.2@880,925 905,925 C12.1@925,905 C12.1@921.22,901.22 ; 905,886 C12.1@921.22,902.22
  Top Layer w24: L13.1@925,845 C12.1@925,897.44
NetC13_1: C13.1 L13.2 L14.1 | length 68.5
  Top Layer w24: L14.1@925,743 C13.1@925,777 L13.2@925,811.54
NetC14_1: C14.1 C15.1 L14.2 | length 67
  Top Layer w20: C15.1@925,644 C15.1@926,643
  Top Layer w24: C15.1@925,644 L14.2@925,709.54
NetC15_2: C15.2 R11.1 R12.1 | length 38
  Top Layer w24: R12.1@926,565 C15.2@926,603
